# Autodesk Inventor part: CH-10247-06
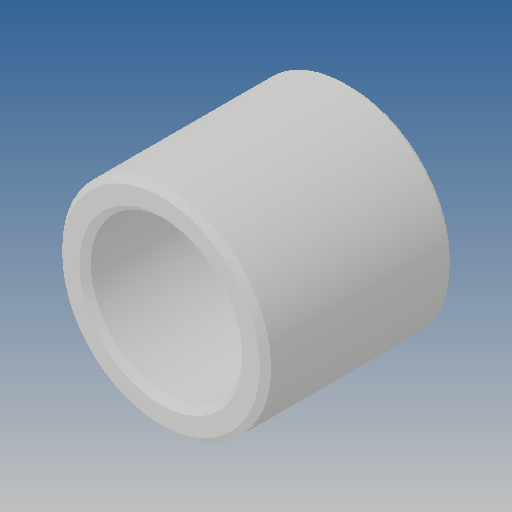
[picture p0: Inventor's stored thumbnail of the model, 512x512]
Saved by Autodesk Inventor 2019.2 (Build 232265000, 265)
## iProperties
Created: 2012-09
Part Number: CH-10247-06
Material: Ogólny
Document SubType Name: Modeling
Designer: CADENGINEERING4
Density: 1 g/cm^3
Appearance: Domyślna
Author: CADENGINEERING4
Revision Number: ÈÎºÎ
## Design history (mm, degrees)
feature "µ¹½Ç1"
node "Bryła1"
